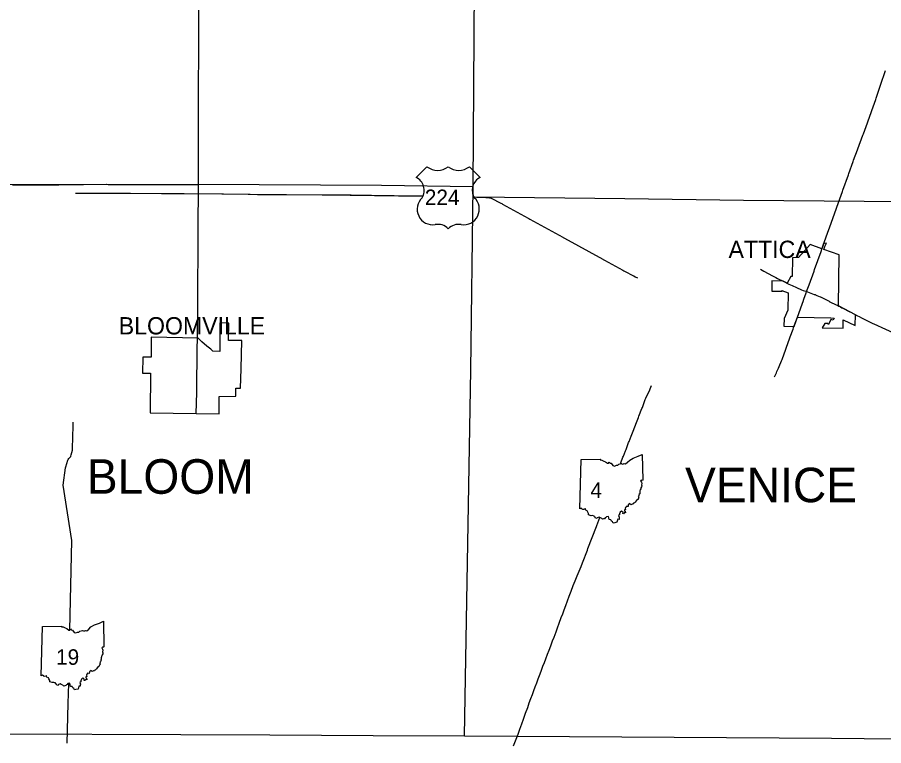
# Model space of a CAD drawing. Extents: x -232 to 448, y 619 to 1059.
# Drawn here: x 309.5 to 360.9, y 682.1 to 725.4 of the extents above; entities that cross this region are included whole.
import ezdxf

# ---------------------------------------------------------------- set-up
doc = ezdxf.new("R2010")
doc.units = 0
doc.layers.add('Default', color=7, linetype='Continuous')

msp = doc.modelspace()

# ---------------------------------------------------------------- linework, layer by layer
at = {"layer": 'Default'}
for p, q in [((333.79, 716.524), (333.155, 715.889)), ((333.79, 716.524), (333.155, 715.889)), ((336.945, 715.889), (336.31, 716.524)), ((336.945, 715.889), (336.31, 716.524)), ((355.791, 707.589), (357.77, 707.537)), ((357.77, 707.537), (357.969, 707.532)), ((357.969, 707.532), (357.92, 707.402)), ((357.264, 706.949), (358.497, 706.933)), ((357.586, 707.182), (357.599, 707.209)), ((357.631, 707.159), (357.586, 707.182)), ((342.87, 696.194), (342.952, 699.122)), ((342.87, 696.194), (342.952, 699.122)), ((310.877, 686.28), (310.959, 689.209)), ((310.877, 686.28), (310.959, 689.209))]:
    msp.add_line(p, q, dxfattribs=at)
for points in [[(336.532, 715.329), (336.743, 748.122)], [(320.213, 715.468), (320.219, 716.931), (320.219, 716.998), (320.221, 718.461), (320.221, 718.535), (320.227, 719.998), (320.227, 720.072), (320.23, 721.48), (320.23, 721.574), (320.232, 722.982), (320.232, 723.08), (320.232, 724.59), (320.234, 726.052), (320.234, 726.133), (320.232, 727.595), (320.232, 727.686), (320.228, 729.078)], [(357.32, 711.861), (357.654, 712.794), (357.689, 712.893), (358.106, 714.067), (358.128, 714.129), (358.456, 715.048), (358.482, 715.123), (358.812, 716.04), (358.843, 716.126), (359.097, 716.841), (359.121, 716.908), (359.349, 717.517), (359.372, 717.579), (359.675, 718.391), (359.706, 718.474), (359.945, 719.136), (359.968, 719.198), (360.196, 719.806), (360.215, 719.858), (360.445, 720.523), (360.47, 720.596), (360.707, 721.317), (360.726, 721.374), (361.023, 722.246)], [(336.532, 715.329), (331.083, 715.405), (320.209, 715.458), (303.672, 715.437)], [(309.167, 715.449), (309.925, 715.451), (309.926, 715.451), (310.034, 715.451), (310.521, 715.452), (310.567, 715.452), (310.629, 715.452), (311.82, 715.453), (311.84, 715.453), (311.929, 715.454), (313.282, 715.462), (313.301, 715.462), (313.39, 715.463), (314.744, 715.476), (314.749, 715.476), (314.852, 715.475), (316.206, 715.466), (316.228, 715.466), (316.314, 715.466), (317.667, 715.47), (317.716, 715.47), (317.776, 715.47), (318.859, 715.466), (318.903, 715.466), (318.967, 715.466), (320.158, 715.468), (320.213, 715.468)], [(320.159, 706.637), (320.176, 708.154), (320.176, 708.164), (320.177, 708.262), (320.206, 712.703), (320.206, 712.733), (320.206, 712.811), (320.213, 715.411), (320.213, 715.468)], [(336.021, 682.71), (336.403, 704.428), (336.532, 715.329)], [(312.912, 714.951), (312.966, 714.951), (314.054, 714.948), (314.1, 714.948), (314.162, 714.948), (316.066, 714.943), (316.099, 714.943), (316.174, 714.943), (318.023, 714.938), (318.043, 714.938), (318.132, 714.936), (318.295, 714.932), (318.35, 714.931), (318.404, 714.931), (319.271, 714.932), (319.286, 714.932), (319.38, 714.931), (321.602, 714.913), (321.609, 714.913), (321.711, 714.911), (323.175, 714.888), (323.175, 714.887), (323.283, 714.886), (323.716, 714.878), (323.771, 714.877), (323.825, 714.877), (325.339, 714.869), (325.345, 714.869), (325.447, 714.868), (327.557, 714.858), (327.57, 714.857), (327.665, 714.857), (328.963, 714.85), (328.981, 714.85), (329.071, 714.848), (329.18, 714.845), (329.235, 714.844), (329.289, 714.844), (330.379, 714.836), (330.392, 714.836), (330.488, 714.834), (331.741, 714.818), (331.749, 714.818), (331.849, 714.817), (333.266, 714.798), (333.269, 714.798), (333.375, 714.797), (333.545, 714.795)], [(333.537, 714.752), (329.231, 714.812)], [(364.55, 714.409), (352.589, 714.523), (345.539, 714.608), (336.612, 714.714)], [(336.616, 714.727), (336.742, 714.723), (336.795, 714.722), (336.85, 714.719), (337.283, 714.697), (337.338, 714.694), (337.392, 714.688), (337.5, 714.675), (337.553, 714.669), (337.602, 714.645), (338.185, 714.352), (338.23, 714.329), (338.281, 714.301), (339.807, 713.466), (339.845, 713.445), (339.902, 713.414), (341.853, 712.337), (341.884, 712.32), (341.948, 712.284), (344.233, 711.026), (344.256, 711.013), (344.328, 710.974), (345.423, 710.37), (345.471, 710.344), (345.519, 710.319), (346.049, 710.041), (346.065, 710.032), (346.146, 709.99), (346.29, 709.913)], [(356.538, 711.892), (355.856, 711.125), (355.497, 711.112)], [(356.481, 709.511), (356.777, 710.326), (356.81, 710.418), (357.188, 711.491), (357.21, 711.554)], [(357.243, 711.647), (356.538, 711.892)], [(357.21, 711.554), (357.215, 711.57), (357.32, 711.861)], [(357.355, 711.959), (357.243, 711.647)], [(357.362, 711.606), (357.419, 711.782), (357.423, 711.781), (357.507, 711.988), (357.355, 711.959)], [(358.265, 711.292), (357.362, 711.606)], [(355.497, 711.112), (355.479, 709.993), (355.401, 709.995), (355.185, 709.6), (354.941, 709.72), (354.264, 709.736), (354.263, 709.134), (354.874, 709.132), (354.864, 709.16), (355.231, 709.025)], [(359.224, 707.087), (359.235, 707.733), (358.231, 708.251), (358.265, 711.292)], [(353.592, 710.43), (353.688, 710.379), (353.702, 710.372), (353.784, 710.327), (354.31, 710.041)], [(354.31, 710.041), (354.501, 709.937), (354.511, 709.932), (354.599, 709.888), (354.941, 709.72)], [(354.941, 709.72), (355.283, 709.552)], [(355.283, 709.552), (355.381, 709.504), (355.386, 709.502), (355.48, 709.459), (355.727, 709.346)], [(356.173, 708.645), (356.307, 709.029), (356.307, 709.029), (356.334, 709.104), (356.481, 709.511)], [(355.231, 709.025), (355.21, 708.007), (354.996, 707.501), (354.99, 707.041), (355.587, 707.038)], [(355.727, 709.346), (356.025, 709.21), (356.026, 709.209), (356.128, 709.174)], [(356.128, 709.174), (356.282, 709.121), (356.334, 709.104), (356.384, 709.085), (356.688, 708.976), (356.691, 708.975), (356.789, 708.94)], [(356.789, 708.94), (356.839, 708.922), (356.866, 708.912), (356.939, 708.882), (357.138, 708.8), (357.167, 708.789), (357.234, 708.753), (357.663, 708.529)], [(355.768, 707.526), (356.093, 708.422), (356.128, 708.517), (356.173, 708.645)], [(357.663, 708.529), (357.673, 708.524), (357.76, 708.482), (358.05, 708.342), (358.085, 708.325), (358.146, 708.294), (358.194, 708.269)], [(358.194, 708.269), (358.242, 708.245), (358.273, 708.229), (358.337, 708.195)], [(358.337, 708.195), (358.432, 708.145), (358.479, 708.12)], [(358.479, 708.12), (358.528, 708.095), (358.867, 707.923), (358.899, 707.906), (358.963, 707.873), (359.35, 707.673), (359.359, 707.668), (359.446, 707.624), (359.592, 707.551)], [(355.561, 706.965), (355.729, 707.418), (355.761, 707.505), (355.768, 707.526)], [(355.587, 707.038), (355.791, 707.589)], [(357.778, 707.439), (357.631, 707.159)], [(357.92, 707.402), (357.778, 707.439)], [(358.497, 706.933), (358.497, 707.431)], [(358.497, 707.431), (359.224, 707.087)], [(359.592, 707.551), (360.222, 707.232), (360.257, 707.214), (360.32, 707.186), (361.709, 706.565)], [(317.415, 706.402), (317.402, 705.214), (316.907, 705.205), (316.895, 704.264), (317.374, 704.253), (317.346, 701.897), (320.088, 701.857), (321.451, 701.847), (321.455, 702.872), (322.444, 702.895), (322.443, 703.37), (322.72, 703.372), (322.751, 704.523), (322.791, 706.191), (322.009, 706.203), (322.019, 707.231), (321.493, 707.246), (321.486, 705.553), (321.079, 705.572), (320.956, 705.682), (320.723, 705.872), (320.423, 706.127), (320.204, 706.344)], [(354.43, 704.041), (354.537, 704.283), (354.57, 704.358), (354.658, 704.556), (354.7, 704.65), (354.848, 704.999), (354.877, 705.068), (355.101, 705.678), (355.127, 705.747), (355.344, 706.359), (355.366, 706.419), (355.53, 706.878), (355.559, 706.96), (355.561, 706.965)], [(357.41, 707.215), (357.264, 706.949)], [(357.599, 707.209), (357.41, 707.215)], [(320.204, 706.344), (317.415, 706.402)], [(320.146, 705.554), (320.157, 706.475)], [(320.157, 706.475), (320.159, 706.637)], [(320.141, 705.175), (320.146, 705.554)], [(320.13, 703.929), (320.14, 705.012), (320.14, 705.025), (320.141, 705.121), (320.141, 705.175)], [(320.124, 703.333), (320.13, 703.929)], [(320.089, 701.871), (320.122, 703.117), (320.122, 703.133), (320.123, 703.225), (320.124, 703.333)], [(345.273, 698.869), (345.293, 698.923), (345.429, 699.277), (345.452, 699.338), (345.572, 699.64), (345.609, 699.731), (345.761, 700.137), (345.788, 700.209), (345.907, 700.511), (345.946, 700.612), (346.067, 700.914), (346.093, 700.98), (346.268, 701.435), (346.303, 701.525), (346.344, 701.625), (346.377, 701.708), (346.557, 702.162), (346.583, 702.229), (346.756, 702.685), (346.791, 702.778), (347.016, 703.271), (347.038, 703.321), (347.128, 703.524)], [(312.588, 688.991), (312.708, 694.323), (312.184, 697.599), (312.318, 698.637), (312.335, 698.689), (312.47, 699.1), (312.481, 699.133), (312.529, 699.189), (312.633, 699.314), (312.644, 699.326), (312.667, 699.415), (312.737, 699.677), (312.743, 699.697), (312.745, 699.784), (312.781, 701.138), (312.782, 701.157), (312.784, 701.246), (312.787, 701.355)], [(342.952, 699.122), (344.088, 699.142), (344.071, 699.106), (344.178, 699.099), (344.292, 699.036), (344.388, 698.997), (344.506, 698.904), (344.576, 698.905), (344.606, 698.981), (344.66, 698.922), (344.724, 698.911), (344.835, 698.771), (344.927, 698.741), (345.036, 698.789), (345.118, 698.797), (345.178, 698.844), (345.334, 698.885), (345.377, 698.861), (345.46, 698.866), (345.501, 698.884), (345.573, 698.867), (345.7, 698.974), (345.831, 699.1), (346.031, 699.218), (346.331, 699.33), (346.568, 699.431), (346.602, 697.911)], [(342.952, 699.122), (344.088, 699.142), (344.071, 699.106), (344.178, 699.099), (344.292, 699.036), (344.388, 698.997), (344.506, 698.904), (344.576, 698.905), (344.606, 698.981), (344.66, 698.922), (344.724, 698.911), (344.835, 698.771), (344.927, 698.741), (345.036, 698.789), (345.118, 698.797), (345.178, 698.844), (345.334, 698.885), (345.377, 698.861), (345.46, 698.866), (345.501, 698.884), (345.573, 698.867), (345.7, 698.974), (345.831, 699.1), (346.031, 699.218), (346.331, 699.33), (346.568, 699.431), (346.602, 697.911)], [(346.602, 697.911), (346.567, 697.889), (346.513, 697.899), (346.476, 697.857), (346.522, 697.786), (346.543, 697.711), (346.524, 697.628), (346.543, 697.559), (346.53, 697.502), (346.496, 697.445), (346.484, 697.391), (346.455, 697.334), (346.457, 697.302), (346.43, 697.277), (346.435, 697.181), (346.421, 697.129), (346.425, 697.083), (346.38, 697.071), (346.391, 697.034), (346.362, 697.005), (346.368, 696.955), (346.336, 696.923), (346.367, 696.859), (346.342, 696.839), (346.321, 696.762), (346.263, 696.746), (346.148, 696.604), (346.107, 696.55), (346.061, 696.537), (346.036, 696.482), (345.979, 696.482), (345.894, 696.444), (345.839, 696.509), (345.742, 696.43), (345.731, 696.339), (345.609, 696.342), (345.614, 696.296), (345.586, 696.282), (345.561, 696.236), (345.576, 696.154), (345.519, 696.133), (345.526, 696.085), (345.562, 696.056), (345.579, 695.965), (345.518, 695.983), (345.468, 695.906), (345.417, 695.924), (345.433, 695.989), (345.347, 696.068), (345.265, 696.005), (345.222, 695.905), (345.222, 695.837), (345.161, 695.797), (345.2, 695.701), (345.193, 695.636), (345.194, 695.574), (345.118, 695.576), (345.071, 695.408)], [(346.602, 697.911), (346.567, 697.889), (346.513, 697.899), (346.476, 697.857), (346.522, 697.786), (346.543, 697.711), (346.524, 697.628), (346.543, 697.559), (346.53, 697.502), (346.496, 697.445), (346.484, 697.391), (346.455, 697.334), (346.457, 697.302), (346.43, 697.277), (346.435, 697.181), (346.421, 697.129), (346.425, 697.083), (346.38, 697.071), (346.391, 697.034), (346.362, 697.005), (346.368, 696.955), (346.336, 696.923), (346.367, 696.859), (346.342, 696.839), (346.321, 696.762), (346.263, 696.746), (346.148, 696.604), (346.107, 696.55), (346.061, 696.537), (346.036, 696.482), (345.979, 696.482), (345.894, 696.444), (345.839, 696.509), (345.742, 696.43), (345.731, 696.339), (345.609, 696.342), (345.614, 696.296), (345.586, 696.282), (345.561, 696.236), (345.576, 696.154), (345.519, 696.133), (345.526, 696.085), (345.562, 696.056), (345.579, 695.965), (345.518, 695.983), (345.468, 695.906), (345.417, 695.924), (345.433, 695.989), (345.347, 696.068), (345.265, 696.005), (345.222, 695.905), (345.222, 695.837), (345.161, 695.797), (345.2, 695.701), (345.193, 695.636), (345.194, 695.574), (345.118, 695.576), (345.071, 695.408)], [(345.071, 695.408), (344.939, 695.375), (344.847, 695.356), (344.814, 695.433), (344.748, 695.473), (344.706, 695.55), (344.611, 695.56), (344.589, 695.666), (344.578, 695.752), (344.449, 695.73), (344.413, 695.678), (344.368, 695.664), (344.341, 695.611), (344.278, 695.607), (344.211, 695.582), (344.167, 695.634), (344.058, 695.686), (344.008, 695.712), (343.905, 695.671), (343.883, 695.621), (343.801, 695.643), (343.781, 695.698), (343.732, 695.715), (343.721, 695.773), (343.614, 695.804), (343.533, 695.792), (343.39, 695.839), (343.381, 695.915), (343.332, 696.009), (343.307, 696.074), (343.216, 696.123), (343.197, 696.201), (343.168, 696.198), (343.142, 696.167), (343.041, 696.153), (343.001, 696.184), (342.945, 696.238), (342.87, 696.194)], [(345.071, 695.408), (344.939, 695.375), (344.847, 695.356), (344.814, 695.433), (344.748, 695.473), (344.706, 695.55), (344.611, 695.56), (344.589, 695.666), (344.578, 695.752), (344.449, 695.73), (344.413, 695.678), (344.368, 695.664), (344.341, 695.611), (344.278, 695.607), (344.211, 695.582), (344.167, 695.634), (344.058, 695.686), (344.008, 695.712), (343.905, 695.671), (343.883, 695.621), (343.801, 695.643), (343.781, 695.698), (343.732, 695.715), (343.721, 695.773), (343.614, 695.804), (343.533, 695.792), (343.39, 695.839), (343.381, 695.915), (343.332, 696.009), (343.307, 696.074), (343.216, 696.123), (343.197, 696.201), (343.168, 696.198), (343.142, 696.167), (343.041, 696.153), (343.001, 696.184), (342.945, 696.238), (342.87, 696.194)], [(338.923, 682.13), (339.043, 682.41), (339.196, 682.817), (339.303, 683.111), (339.416, 683.427), (339.52, 683.7), (339.65, 684.053), (339.786, 684.404), (339.865, 684.674), (339.959, 684.925), (340.048, 685.162), (340.141, 685.413), (340.222, 685.629), (340.309, 685.86), (340.397, 686.097), (340.474, 686.298), (340.574, 686.564), (340.679, 686.844), (340.766, 687.074), (340.844, 687.28), (340.954, 687.57), (341.041, 687.801), (341.138, 688.057), (341.252, 688.357), (341.337, 688.582), (341.456, 688.896), (341.545, 689.137), (341.644, 689.403), (341.767, 689.738), (341.849, 689.96), (341.939, 690.205), (342.031, 690.452), (342.139, 690.743), (342.239, 691.013), (342.345, 691.299), (342.475, 691.648), (342.58, 691.931), (342.702, 692.222), (342.818, 692.497), (342.936, 692.778), (343.023, 692.986), (343.315, 693.745), (343.351, 693.838), (343.849, 695.155), (343.872, 695.216), (344.054, 695.687)], [(310.959, 689.209), (312.096, 689.228), (312.078, 689.193), (312.185, 689.185), (312.299, 689.123), (312.395, 689.083), (312.513, 688.99), (312.584, 688.991), (312.613, 689.067), (312.667, 689.008), (312.731, 688.998), (312.842, 688.858), (312.934, 688.827), (313.043, 688.875), (313.125, 688.883), (313.185, 688.931), (313.341, 688.971), (313.384, 688.947), (313.467, 688.952), (313.508, 688.97), (313.581, 688.954), (313.707, 689.06), (313.838, 689.186), (314.038, 689.304), (314.338, 689.417), (314.575, 689.517), (314.61, 687.997)], [(310.959, 689.209), (312.096, 689.228), (312.078, 689.193), (312.185, 689.185), (312.299, 689.123), (312.395, 689.083), (312.513, 688.99), (312.584, 688.991), (312.613, 689.067), (312.667, 689.008), (312.731, 688.998), (312.842, 688.858), (312.934, 688.827), (313.043, 688.875), (313.125, 688.883), (313.185, 688.931), (313.341, 688.971), (313.384, 688.947), (313.467, 688.952), (313.508, 688.97), (313.581, 688.954), (313.707, 689.06), (313.838, 689.186), (314.038, 689.304), (314.338, 689.417), (314.575, 689.517), (314.61, 687.997)], [(314.61, 687.997), (314.575, 687.976), (314.52, 687.986), (314.483, 687.943), (314.529, 687.872), (314.55, 687.797), (314.531, 687.714), (314.55, 687.646), (314.537, 687.589), (314.503, 687.532), (314.491, 687.477), (314.462, 687.42), (314.464, 687.388), (314.437, 687.363), (314.442, 687.268), (314.428, 687.215), (314.433, 687.17), (314.388, 687.158), (314.398, 687.12), (314.369, 687.091), (314.375, 687.041), (314.343, 687.01), (314.374, 686.946), (314.349, 686.926), (314.328, 686.848), (314.27, 686.832), (314.155, 686.69), (314.114, 686.637), (314.068, 686.623), (314.043, 686.568), (313.987, 686.568), (313.901, 686.53), (313.846, 686.596), (313.749, 686.517), (313.738, 686.425), (313.616, 686.428), (313.621, 686.382), (313.593, 686.369), (313.569, 686.322), (313.583, 686.24), (313.526, 686.219), (313.533, 686.171), (313.569, 686.142), (313.586, 686.051), (313.525, 686.07), (313.475, 685.993), (313.424, 686.011), (313.441, 686.076), (313.354, 686.154), (313.272, 686.091), (313.229, 685.991), (313.229, 685.924), (313.168, 685.883), (313.207, 685.788), (313.2, 685.722), (313.201, 685.66), (313.125, 685.662), (313.079, 685.494)], [(314.61, 687.997), (314.575, 687.976), (314.52, 687.986), (314.483, 687.943), (314.529, 687.872), (314.55, 687.797), (314.531, 687.714), (314.55, 687.646), (314.537, 687.589), (314.503, 687.532), (314.491, 687.477), (314.462, 687.42), (314.464, 687.388), (314.437, 687.363), (314.442, 687.268), (314.428, 687.215), (314.433, 687.17), (314.388, 687.158), (314.398, 687.12), (314.369, 687.091), (314.375, 687.041), (314.343, 687.01), (314.374, 686.946), (314.349, 686.926), (314.328, 686.848), (314.27, 686.832), (314.155, 686.69), (314.114, 686.637), (314.068, 686.623), (314.043, 686.568), (313.987, 686.568), (313.901, 686.53), (313.846, 686.596), (313.749, 686.517), (313.738, 686.425), (313.616, 686.428), (313.621, 686.382), (313.593, 686.369), (313.569, 686.322), (313.583, 686.24), (313.526, 686.219), (313.533, 686.171), (313.569, 686.142), (313.586, 686.051), (313.525, 686.07), (313.475, 685.993), (313.424, 686.011), (313.441, 686.076), (313.354, 686.154), (313.272, 686.091), (313.229, 685.991), (313.229, 685.924), (313.168, 685.883), (313.207, 685.788), (313.2, 685.722), (313.201, 685.66), (313.125, 685.662), (313.079, 685.494)], [(313.079, 685.494), (312.946, 685.462), (312.854, 685.443), (312.821, 685.519), (312.756, 685.559), (312.713, 685.636), (312.618, 685.647), (312.596, 685.752), (312.585, 685.838), (312.456, 685.817), (312.42, 685.764), (312.375, 685.75), (312.348, 685.697), (312.286, 685.693), (312.219, 685.668), (312.175, 685.72), (312.065, 685.772), (312.015, 685.799), (311.912, 685.757), (311.89, 685.708), (311.808, 685.73), (311.789, 685.785), (311.739, 685.801), (311.728, 685.859), (311.622, 685.89), (311.54, 685.878), (311.397, 685.925), (311.388, 686.002), (311.339, 686.095), (311.314, 686.16), (311.223, 686.21), (311.205, 686.287), (311.176, 686.285), (311.149, 686.253), (311.048, 686.239), (311.008, 686.271), (310.952, 686.324), (310.877, 686.28)], [(313.079, 685.494), (312.946, 685.462), (312.854, 685.443), (312.821, 685.519), (312.756, 685.559), (312.713, 685.636), (312.618, 685.647), (312.596, 685.752), (312.585, 685.838), (312.456, 685.817), (312.42, 685.764), (312.375, 685.75), (312.348, 685.697), (312.286, 685.693), (312.219, 685.668), (312.175, 685.72), (312.065, 685.772), (312.015, 685.799), (311.912, 685.757), (311.89, 685.708), (311.808, 685.73), (311.789, 685.785), (311.739, 685.801), (311.728, 685.859), (311.622, 685.89), (311.54, 685.878), (311.397, 685.925), (311.388, 686.002), (311.339, 686.095), (311.314, 686.16), (311.223, 686.21), (311.205, 686.287), (311.176, 686.285), (311.149, 686.253), (311.048, 686.239), (311.008, 686.271), (310.952, 686.324), (310.877, 686.28)], [(312.422, 682.281), (312.49, 684.644), (312.517, 685.827)], [(357.804, 682.576), (359.761, 682.564), (365.926, 682.539), (365.946, 683.788), (372.66, 683.625)], [(303.318, 682.855), (324.457, 682.781), (330.596, 682.743)], [(330.596, 682.743), (336.021, 682.71)], [(336.021, 682.71), (357.804, 682.576)]]:
    msp.add_lwpolyline(points, dxfattribs=at)
for centre, radius, start, end in [((334.42, 717.325), 1.019, 231.813, 308.187), ((334.42, 717.325), 1.019, 231.813, 308.187), ((335.68, 717.325), 1.019, 231.813, 308.187), ((335.68, 717.325), 1.019, 231.813, 308.187), ((332.759, 715.124), 0.862, 329.1175, 62.6108), ((332.759, 715.124), 0.862, 329.1175, 62.6108), ((337.341, 715.124), 0.862, 117.3892, 210.8825), ((337.341, 715.124), 0.862, 117.3892, 210.8825), ((334.133, 714.001), 0.93, 133.0046, 278.7282), ((334.133, 714.001), 0.93, 133.0046, 278.7282), ((335.967, 714.001), 0.93, 261.2718, 46.9954), ((335.967, 714.001), 0.93, 261.2718, 46.9954), ((334.446, 712.267), 0.832, 43.4177, 101.8742), ((334.446, 712.267), 0.832, 43.4177, 101.8742), ((335.672, 712.212), 0.883, 79.9613, 134.7468), ((335.672, 712.212), 0.883, 79.9613, 134.7468)]:
    msp.add_arc(centre, radius, start, end, dxfattribs=at)

# ---------------------------------------------------------------- texts
for s, height, p in [('224', 0.9234, (333.661, 714.24)), ('ATTICA', 1.026, (351.697, 711.102)), ('BLOOMVILLE', 1.026, (315.486, 706.56)), ('BLOOM', 2.052, (313.59, 697.094)), ('VENICE', 2.052, (349.115, 696.591)), (' 4 ', 0.9234, (343.153, 696.847)), ('19', 0.9234, (311.763, 686.933))]:
    msp.add_text(s, height=height, dxfattribs=at).set_placement(p)

doc.saveas('drawing.dxf')
